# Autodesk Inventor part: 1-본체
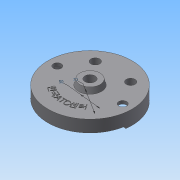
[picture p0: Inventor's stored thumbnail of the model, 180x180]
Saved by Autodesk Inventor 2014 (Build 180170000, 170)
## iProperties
Created: 2015-06
Part Number: 1-본체
Material: Generic
Document SubType Name: Modeling
Designer: Administrator
Density: 1 g/cm^3
Appearance: Default
Author: Administrator
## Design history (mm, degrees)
sketch "스케치1"
  geometry: C1 r 95 at (0, 0); 1 further point
  constraints: 1 centre point, 1 coincident
  dimensions: "d0" = 190 diameter of C1
extrude "돌출1" new body sketch "스케치1" distance "d1" = 32; taper "d2" = 0 deg
sketch "스케치2"
  geometry: L1 (-95, 0)-(0, 0); L2 (0, 0)-(95, 0); L3 (0, 0)-(-94.075, -13.221); L4 (0, 0)-(94.075, -13.221); A1 r 95 centre (0, 0) between (-95, 0) and (95, 0) reference
  constraints: 8 end point, 4 point on circle, 1 collinear, 1 horizontal
  dimensions: "d3" = 8 deg angle of L2 L4; "d4" = 8 deg angle of L1 L3
extrude "돌출2" cut sketch "스케치2" distance "d5" = 5; taper "d6" = 0 deg
sketch "스케치3"
  geometry: L1 (-94.075, -13.221)-(0, 0) reference; L2 (0, 0)-(94.075, -13.221) reference; L3 (-76.358, -3.663)-(-41.984, 1.168); L4 (41.984, 1.168)-(76.358, -3.663); A1 r 95 centre (0, 0) between (94.075, -13.221) and (-94.075, -13.221) reference; A2 r 88 centre (0, 0) between (87.718, 7.04) and (-87.718, 7.04); A3 r 42 centre (0, 0) between (41.984, 1.168) and (-41.984, 1.168); A4 r 10 centre (-77.75, 6.24) between (-87.718, 7.04) and (-76.358, -3.663); A5 r 10 centre (77.75, 6.24) between (76.358, -3.663) and (87.718, 7.04); 2 further points
  constraints: 10 point on circle, 4 centre point, 4 end point, 4 tangent, 2 point on line, 1 coincident, 1 equal radius
  dimensions: "d8" = 84 diameter of A3; "d9" = 7 radial gap between concentric circles of A1 A2; "d10" = 10 radius of A4; "d13" = 7 distance between parallel lines of L3 L1; "d14" = 7 distance between parallel lines of L4 L2
extrude "돌출4" cut sketch "스케치3" distance "d15" = 25; taper "d16" = 0 deg
fillet "모깎기1" dims "d17" = 10
sketch "스케치4"
  geometry: C1 r 95 at (0, 0) reference; C2 r 26 at (0, 0)
  constraints: 1 centre point, 1 coincident
  dimensions: "d18" = 52 diameter of C2
extrude "돌출5" join sketch "스케치4" distance "d19" = 12; taper "d20" = -15 deg
hole "구멍1" diameter "d23" = 23; stored, may be unused: countersink angle "d27" = 90 deg, drill point angle "d29" = 118 deg; dims "d21" = 10, "d22" = 10, "d24" = 6, "d25" = 4, "d26" = 2, "d28" = 8
sketch "스케치5"
  geometry: C1 r 26 at (0, 0) reference; 2 further points
  constraints: 1 horizontal alignment
  dimensions: "d30" = 52 vertical distance of C1.centre point (40, 52); "d31" = 40 horizontal distance of C1.centre point (-40, 52); "d32" = 40 horizontal distance of point (40, 52) C1.centre
hole "구멍2" sketch "스케치5" at (-40, 52), (40, 52) diameter "d33" = 20; stored, may be unused: countersink angle "d37" = 90 deg, drill point angle "d39" = 118 deg; dims "d34" = 6, "d35" = 4, "d36" = 2, "d38" = 8
sketch "스케치6"
  geometry: C1 r 10 at (40, 52) reference; C2 r 10 at (-40, 52) reference; C3 r 15 at (-40, 52); C4 r 15 at (40, 52)
  constraints: 2 centre point, 2 coincident, 1 equal radius
  dimensions: "d40" = 30 diameter of C3
extrude "돌출6" join sketch "스케치6" distance "d41" = 25; taper "d42" = 0 deg
sketch "스케치7"
  geometry: L1 (-6, 15)-(6, 15); L2 (6, 15)-(6, -15); L3 (6, -15)-(-6, -15); L4 (-6, -15)-(-6, 15); L5 (-6, 15)-(6, -15); L6 (6, 15)-(-6, -15); L7 (74, 15)-(86, 15); L8 (86, 15)-(86, -15); L9 (86, -15)-(74, -15); L10 (74, -15)-(74, 15); L11 (74, 15)-(86, -15); L12 (86, 15)-(74, -15); C1 r 15 at (0, 0) reference; C2 r 15 at (80, 0) reference; 1 further point
  constraints: 24 end point, 4 midpoint, 4 parallel, 2 equal length, 2 horizontal, 2 perpendicular
  dimensions: "d43" = 12 distance of L1.start L1.end; "d44" = 30 distance of L1.end L2.end
extrude "돌출7" cut sketch "스케치7" distance "d45" = 3; taper "d46" = 0 deg
sketch "스케치8"
  geometry: C1 r 25 at (0, 0); C2 r 35 at (0, 0); A1 r 88 centre (0, 0) between (87.718, 7.04) and (-87.718, 7.04) reference
  constraints: 2 centre point, 2 coincident
  dimensions: "d47" = 70 diameter of C2; "d48" = 50 diameter of C1
extrude "돌출8" cut sketch "스케치8" stored distance "d49" = 15; taper "d50" = 0 deg
sketch "스케치9"
  geometry: C1 r 10 at (40, 52) reference; C2 r 95 at (0, 0) reference; A1 r 74 centre (0, 0) between (74, 0) and (-74, 0)
  constraints: 2 point on circle, 1 centre point, 1 coincident, 1 horizontal alignment
  dimensions: "d51" = 52 vertical distance of C1.centre A1.start; "d52" = 148 diameter of A1
hole "구멍3" sketch "스케치9" at (-74, 0), (74, 0) diameter "d53" = 11; stored, may be unused: countersink angle "d57" = 90 deg, drill point angle "d59" = 118 deg; dims "d54" = 6, "d55" = 18, "d56" = 11, "d58" = 8
sketch "스케치10"
  geometry: C1 r 95 at (0, 0) reference; C2 r 68 at (0, 0)
  constraints: 1 centre point, 1 coincident, 1 other
  dimensions: "d60" = 136 diameter of C2
feature "엠보싱1" sketch "스케치10" dims "d10" = 10, "d61" = 0.5, "d62" = 0
sketch "스케치11"
  geometry: L1 (-94.075, -13.221)-(-24.757, -3.479) reference; L2 (24.757, -3.479)-(94.075, -13.221) reference; A1 r 25 centre (0, 0) between (-24.757, -3.479) and (24.757, -3.479) reference; A2 r 95 centre (0, 0) between (-94.075, -13.221) and (94.075, -13.221) reference; A3 r 41 centre (0, -19) between (-40.794, -14.9) and (40.794, -14.9); A4 r 59 centre (0, -19) between (-58.704, -13.1) and (58.704, -13.1); A5 r 9 centre (-49.749, -14) between (-40.794, -14.9) and (-58.704, -13.1); A6 r 9 centre (49.749, -14) between (58.704, -13.1) and (40.794, -14.9)
  constraints: 8 point on circle, 4 centre point, 2 tangent, 1 coincident, 1 equal radius, 1 vertical alignment
  dimensions: "d63" = 82 diameter of A3; "d64" = 118 diameter of A4; "d65" = 19 distance of A3.centre A1.centre; "d66" = 18 diameter of A5; "d70" = 5 vertical distance of A5.centre A3.centre; "d71" = 5 vertical distance of A6.centre A3.centre
node "솔리드1"
